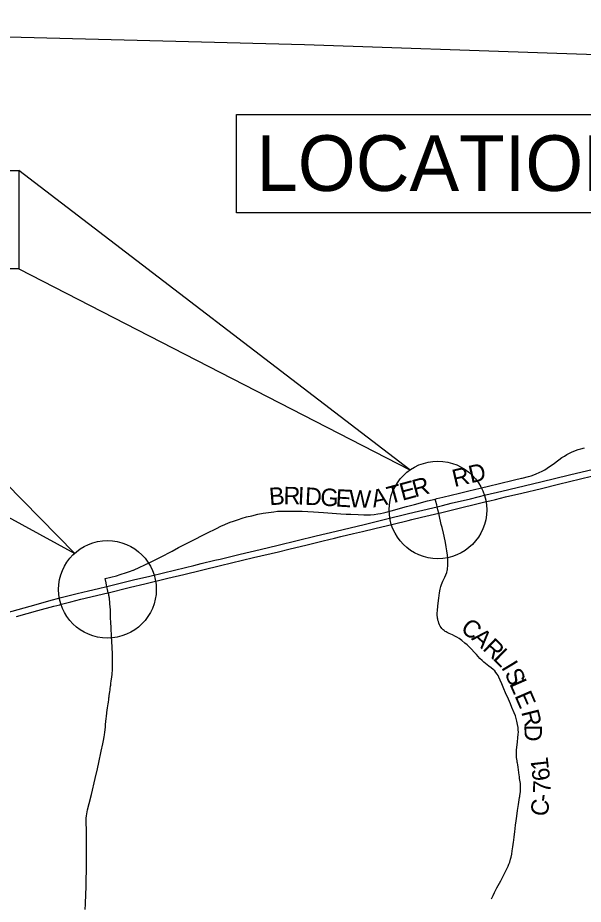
# Model space of a CAD drawing. Extents: x -29.6 to 34, y 0 to 22.
# Drawn here: x -14.201 to -12.475, y 3.392 to 6.1 of the extents above; entities that cross this region are included whole.
import ezdxf

# ---------------------------------------------------------------- set-up
doc = ezdxf.new("R2010")
doc.units = 0
for name, color, linetype in [('BR_P_Gen_Text', 7, 'Continuous'), ('Default', 7, 'Continuous'), ('GM_X_County_Road', 7, 'Continuous'), ('GM_X_County_Road_Text', 7, 'Continuous'), ('GM_X_Interstate_Location', 7, 'Continuous'), ('GM_X_Interstate_Route', 7, 'Continuous'), ('GM_X_Township', 7, 'Continuous'), ('GM_X_US_Route', 7, 'Continuous')]:
    doc.layers.add(name, color=color, linetype=linetype)

msp = doc.modelspace()

# ---------------------------------------------------------------- linework, layer by layer
at = {"layer": 'BR_P_Gen_Text'}
for points in [[(-13.5333, 5.8042), (-12.1246, 5.8042), (-12.1246, 5.504), (-13.5333, 5.504)], [(-15.6064, 5.6331), (-14.1976, 5.6331), (-14.1976, 5.3329), (-15.6064, 5.3329)], [(-14.1976, 5.6331), (-14.1976, 5.3329), (-13.0043, 4.7188)], [(-14.6646, 5.1118), (-14.6646, 4.8115), (-14.027, 4.4641)]]:
    msp.add_lwpolyline(points, close=True, dxfattribs=at)
at = {"layer": 'Default'}
for centre in [(-12.9184, 4.5966), (-13.9274, 4.3541)]:
    msp.add_circle(centre, 0.149, dxfattribs=at)
at = {"layer": 'GM_X_County_Road'}
for points in [[(-12.6637, 4.6933), (-12.6607, 4.694), (-12.6421, 4.6986), (-12.6332, 4.7012), (-12.6255, 4.7039), (-12.6185, 4.7066), (-12.6089, 4.7108), (-12.6, 4.715), (-12.5924, 4.7192), (-12.585, 4.7237), (-12.5773, 4.7289), (-12.5665, 4.7368), (-12.5488, 4.7501), (-12.5398, 4.7566), (-12.5324, 4.7613), (-12.5243, 4.766), (-12.517, 4.7698), (-12.5101, 4.7729), (-12.4982, 4.7779), (-12.49, 4.781), (-12.4817, 4.7837), (-12.471, 4.7865)], [(-12.9269, 4.6299), (-12.9217, 4.6312), (-12.9036, 4.6356), (-12.8775, 4.6419), (-12.852, 4.648), (-12.8243, 4.6546), (-12.7898, 4.663), (-12.7603, 4.6699), (-12.7349, 4.6763), (-12.6845, 4.6884), (-12.6637, 4.6933)], [(-13.5495, 4.5601), (-13.5451, 4.5618), (-13.5274, 4.5679), (-13.5163, 4.5714), (-13.5028, 4.5751), (-13.487, 4.5791), (-13.4682, 4.5834), (-13.4516, 4.5868), (-13.4361, 4.5893), (-13.4199, 4.5913), (-13.4082, 4.5924), (-13.3995, 4.593), (-13.3867, 4.5934), (-13.3721, 4.5934), (-13.3552, 4.5932), (-13.333, 4.5924), (-13.2981, 4.5906), (-13.2679, 4.5887), (-13.2417, 4.5872), (-13.2144, 4.5852), (-13.1981, 4.5842), (-13.1842, 4.5837), (-13.1621, 4.5826), (-13.1446, 4.5819), (-13.1336, 4.5818), (-13.1238, 4.5822), (-13.1133, 4.5831), (-13.1018, 4.5845), (-13.0938, 4.5858), (-13.0842, 4.5878), (-13.0763, 4.5897), (-13.0611, 4.5938), (-13.014, 4.607), (-12.9899, 4.6137), (-12.9505, 4.624), (-12.9269, 4.6299)], [(-12.908, 4.5526), (-12.9148, 4.5814), (-12.9161, 4.5869), (-12.9184, 4.5966), (-12.9208, 4.6064), (-12.9222, 4.6119), (-12.9248, 4.622), (-12.9269, 4.6299)], [(-13.772, 4.4496), (-13.7655, 4.4529), (-13.7303, 4.4711), (-13.7101, 4.4815), (-13.6739, 4.5003), (-13.6236, 4.5261), (-13.5948, 4.5402), (-13.5817, 4.5466), (-13.5695, 4.5522), (-13.5576, 4.5571), (-13.5495, 4.5601)], [(-12.8895, 4.4142), (-12.8887, 4.4181), (-12.8879, 4.4257), (-12.8877, 4.4326), (-12.8878, 4.4396), (-12.8883, 4.4489), (-12.8892, 4.4582), (-12.8909, 4.4715), (-12.8928, 4.4836), (-12.8941, 4.4911), (-12.8963, 4.5019), (-12.9015, 4.5257), (-12.9056, 4.5426), (-12.908, 4.5526)], [(-13.8492, 4.4126), (-13.8477, 4.4132), (-13.8285, 4.4215), (-13.8153, 4.4277), (-13.7955, 4.4376), (-13.772, 4.4496)], [(-12.7553, 3.4088), (-12.7502, 3.4197), (-12.7459, 3.428), (-12.7382, 3.4429), (-12.7268, 3.4639), (-12.7214, 3.4742), (-12.7173, 3.4819), (-12.7151, 3.486), (-12.7088, 3.4985), (-12.7038, 3.509), (-12.7015, 3.5144), (-12.6991, 3.5209), (-12.6963, 3.5298), (-12.6946, 3.5366), (-12.6929, 3.5452), (-12.6912, 3.5561), (-12.6896, 3.5676), (-12.6876, 3.582), (-12.6869, 3.5883), (-12.6858, 3.5986), (-12.684, 3.614), (-12.6829, 3.6238), (-12.6816, 3.6341), (-12.6799, 3.6468), (-12.6778, 3.6618), (-12.6755, 3.6786), (-12.6726, 3.6976), (-12.6693, 3.7183), (-12.6686, 3.7215), (-12.6682, 3.7243), (-12.6665, 3.7356), (-12.6661, 3.7407), (-12.666, 3.7548), (-12.6662, 3.7586), (-12.6664, 3.7609), (-12.6691, 3.7768), (-12.6697, 3.7815), (-12.6713, 3.7942), (-12.6725, 3.8036), (-12.6736, 3.8104), (-12.6748, 3.8191), (-12.6755, 3.8231), (-12.6758, 3.8242), (-12.676, 3.8253), (-12.6769, 3.8304), (-12.6781, 3.8409), (-12.6787, 3.849), (-12.6788, 3.856), (-12.6786, 3.8629), (-12.6777, 3.8722), (-12.6768, 3.8791), (-12.6755, 3.8884), (-12.674, 3.9005), (-12.6731, 3.9115), (-12.6728, 3.9185), (-12.6731, 3.9255), (-12.6738, 3.9325), (-12.6753, 3.9417), (-12.6773, 3.9514), (-12.6794, 3.9598), (-12.6818, 3.9676), (-12.6851, 3.977), (-12.6923, 3.9937), (-12.6969, 4.0045), (-12.7031, 4.0189), (-12.712, 4.0384), (-12.7171, 4.0499), (-12.7237, 4.0656), (-12.7285, 4.0769), (-12.7325, 4.0859), (-12.7348, 4.0906), (-12.7378, 4.0956), (-12.7412, 4.1004), (-12.745, 4.1048), (-12.7496, 4.1093), (-12.7557, 4.1146), (-12.7626, 4.1193), (-12.7733, 4.1272), (-12.7784, 4.1318), (-12.7837, 4.1365), (-12.7905, 4.1432), (-12.8007, 4.1547), (-12.8078, 4.1628), (-12.8155, 4.1713), (-12.8225, 4.1786), (-12.8287, 4.1842), (-12.8363, 4.1902), (-12.8456, 4.1976), (-12.8539, 4.2041), (-12.8604, 4.2081), (-12.8665, 4.2114), (-12.8737, 4.2151), (-12.8837, 4.2196), (-12.89, 4.2226), (-12.8931, 4.2242), (-12.896, 4.2259), (-12.8975, 4.2268), (-12.8993, 4.2282), (-12.902, 4.2304), (-12.9037, 4.232), (-12.9061, 4.2345), (-12.9086, 4.2377), (-12.9112, 4.2416), (-12.9137, 4.2462), (-12.9155, 4.2505), (-12.917, 4.2555), (-12.9182, 4.26), (-12.919, 4.2635), (-12.9195, 4.2657), (-12.92, 4.2686), (-12.9204, 4.2756), (-12.9204, 4.2826), (-12.92, 4.2889), (-12.9184, 4.304), (-12.9154, 4.3271), (-12.9132, 4.3433), (-12.9113, 4.3548), (-12.9095, 4.3627), (-12.9077, 4.3689), (-12.9058, 4.3738), (-12.9034, 4.3791), (-12.8971, 4.3915), (-12.894, 4.3985), (-12.8916, 4.4056), (-12.8901, 4.4113), (-12.8895, 4.4142)], [(-13.9347, 4.3868), (-13.9175, 4.3912), (-13.9, 4.3956), (-13.8883, 4.3991), (-13.8689, 4.4052), (-13.8601, 4.4083), (-13.8492, 4.4126)], [(-13.9206, 4.3181), (-13.9208, 4.3203), (-13.9212, 4.3225), (-13.9216, 4.327), (-13.9221, 4.3298), (-13.9226, 4.3332), (-13.923, 4.3348), (-13.9236, 4.3382), (-13.9248, 4.3438), (-13.9258, 4.3483), (-13.9292, 4.3631), (-13.9302, 4.3672), (-13.9318, 4.3739), (-13.9347, 4.3868)], [(-13.9953, 3.376), (-13.9945, 3.3926), (-13.9942, 3.4037), (-13.9938, 3.413), (-13.9934, 3.4212), (-13.993, 3.4316), (-13.9929, 3.4368), (-13.9928, 3.4444), (-13.9922, 3.4746), (-13.9918, 3.4891), (-13.9917, 3.5136), (-13.9917, 3.5346), (-13.9918, 3.5497), (-13.9916, 3.5713), (-13.9912, 3.5911), (-13.9913, 3.6033), (-13.9918, 3.6213), (-13.9926, 3.6394), (-13.9927, 3.6499), (-13.9925, 3.6552), (-13.9917, 3.6622), (-13.9906, 3.6685), (-13.9879, 3.6805), (-13.983, 3.7003), (-13.9765, 3.7281), (-13.9653, 3.7763), (-13.9582, 3.8058), (-13.9537, 3.8257), (-13.9464, 3.8604), (-13.942, 3.8821), (-13.9398, 3.8929), (-13.9378, 3.9038), (-13.9369, 3.9095), (-13.9358, 3.9182), (-13.9349, 3.9251), (-13.9338, 3.9343), (-13.9332, 3.94), (-13.932, 3.9515), (-13.9311, 3.959), (-13.9302, 3.9671), (-13.9279, 3.9862), (-13.9273, 3.9908), (-13.9262, 3.9994), (-13.9255, 4.004), (-13.9247, 4.0103), (-13.9237, 4.0166), (-13.9228, 4.0229), (-13.9224, 4.0257), (-13.9217, 4.0303), (-13.9203, 4.0407), (-13.9194, 4.047), (-13.9189, 4.0504), (-13.9177, 4.0585), (-13.9173, 4.0614), (-13.9166, 4.0677), (-13.9156, 4.0734), (-13.9148, 4.0804), (-13.9141, 4.0855), (-13.9139, 4.0867), (-13.9134, 4.0936), (-13.9128, 4.0994), (-13.9124, 4.1057), (-13.9119, 4.1162), (-13.9119, 4.1254), (-13.9122, 4.1406), (-13.9125, 4.1556), (-13.9134, 4.1781), (-13.9151, 4.2103), (-13.9164, 4.2362), (-13.9171, 4.2535), (-13.9177, 4.2663), (-13.9179, 4.275), (-13.918, 4.2849), (-13.9184, 4.2901), (-13.9192, 4.3022), (-13.9197, 4.3085), (-13.9199, 4.3111), (-13.9201, 4.3127), (-13.9202, 4.3148), (-13.9205, 4.317), (-13.9206, 4.3181)]]:
    msp.add_lwpolyline(points, dxfattribs=at)
at = {"layer": 'GM_X_Interstate_Route'}
for points in [[(-14.2365, 4.2822), (-14.1452, 4.3082), (-14.1065, 4.3189), (-14.0688, 4.3288), (-14.0203, 4.3412), (-13.9857, 4.3494), (-13.9551, 4.3568), (-13.9292, 4.3631), (-13.8969, 4.371), (-13.8482, 4.3828), (-13.7977, 4.3948), (-13.7558, 4.4049), (-13.6896, 4.421), (-13.6636, 4.4273), (-13.6415, 4.4326), (-13.5996, 4.4428), (-13.5832, 4.4468), (-13.5225, 4.4612), (-13.4614, 4.476), (-13.4059, 4.4892), (-13.2898, 4.5173), (-13.2286, 4.5321), (-13.1437, 4.5525), (-13.0786, 4.5682), (-13.0084, 4.5853), (-12.9342, 4.603), (-12.9212, 4.6063), (-12.9042, 4.6105), (-12.8776, 4.6169), (-12.8193, 4.6308), (-12.7717, 4.6425), (-12.723, 4.6542), (-12.6296, 4.6766), (-12.5667, 4.6918), (-12.5124, 4.705), (-12.4478, 4.7204)], [(-14.2047, 4.271), (-14.1402, 4.2893), (-14.0907, 4.3027), (-14.0733, 4.3073), (-14.0722, 4.3076), (-14.0395, 4.3161), (-14.009, 4.3238), (-13.9263, 4.3437), (-13.9248, 4.344), (-13.9248, 4.344), (-13.9093, 4.3477), (-13.877, 4.3555), (-13.8566, 4.3604), (-13.813, 4.3708), (-13.7428, 4.3878), (-13.6941, 4.3995), (-13.582, 4.4267), (-13.4818, 4.4509), (-13.4047, 4.4692), (-13.3736, 4.4768), (-13.3175, 4.4904), (-13.2688, 4.5021), (-13.2343, 4.5105), (-13.215, 4.5151), (-13.1765, 4.5244), (-13.1482, 4.5311), (-13.1108, 4.5401), (-13.0553, 4.5534), (-13.0088, 4.5646), (-12.9981, 4.5672), (-12.9681, 4.5745), (-12.9161, 4.5869), (-12.9103, 4.5883), (-12.8944, 4.5921), (-12.8537, 4.6019), (-12.7993, 4.615), (-12.7749, 4.6209), (-12.7597, 4.6246), (-12.7421, 4.6288), (-12.7116, 4.6363), (-12.6623, 4.6481), (-12.6022, 4.6625), (-12.5507, 4.6751), (-12.4828, 4.6916), (-12.416, 4.7078)]]:
    msp.add_lwpolyline(points, dxfattribs=at)
at = {"layer": 'GM_X_Township'}
msp.add_lwpolyline([(-16.907, 6.0998), (-16.7922, 6.098), (-15.3983, 6.0749), (-14.5953, 6.0489), (-14.3095, 6.0432), (-13.3257, 6.0175), (-12.5552, 5.9919), (-12.2845, 5.982)], dxfattribs=at)
at = {"layer": 'GM_X_US_Route'}
msp.add_lwpolyline([(-14.2047, 4.271), (-14.1402, 4.2893), (-14.0907, 4.3027), (-14.0733, 4.3073), (-14.0722, 4.3076), (-14.0395, 4.3161), (-14.009, 4.3238), (-13.9263, 4.3437), (-13.9248, 4.344), (-13.9248, 4.344), (-13.9093, 4.3477), (-13.877, 4.3555), (-13.8566, 4.3604), (-13.813, 4.3708), (-13.7428, 4.3878), (-13.6941, 4.3995), (-13.582, 4.4267), (-13.4818, 4.4509), (-13.4047, 4.4692), (-13.3736, 4.4768), (-13.3175, 4.4904), (-13.2688, 4.5021), (-13.2343, 4.5105), (-13.215, 4.5151), (-13.1765, 4.5244), (-13.1482, 4.5311), (-13.1108, 4.5401), (-13.0553, 4.5534), (-13.0088, 4.5646), (-12.9981, 4.5672), (-12.9681, 4.5745), (-12.9161, 4.5869), (-12.9103, 4.5883), (-12.8944, 4.5921), (-12.8537, 4.6019), (-12.7993, 4.615), (-12.7749, 4.6209), (-12.7597, 4.6246), (-12.7421, 4.6288), (-12.7116, 4.6363), (-12.6623, 4.6481), (-12.6022, 4.6625), (-12.5507, 4.6751), (-12.4828, 4.6916), (-12.416, 4.7078)], dxfattribs=at)

# ---------------------------------------------------------------- texts
at = {"layer": 'BR_P_Gen_Text'}
msp.add_text('LOCATION 1', height=0.17, dxfattribs=at).set_placement((-13.4726, 5.5708))
at = {"layer": 'GM_X_County_Road_Text'}
for s, height, rotation, p in [('RD', 0.05327, 13.2138, (-12.8679, 4.6661)), ('E', 0.0533, 15.0376, (-13.0273, 4.6244)), ('R', 0.0533, 14.989, (-12.9889, 4.6347)), ('B', 0.0533, 4.3959, (-13.432, 4.6107)), ('R', 0.0533, 359.5212, (-13.3899, 4.614)), ('I', 0.0533, 357.5435, (-13.347, 4.6136)), ('D', 0.0533, 356.9161, (-13.3254, 4.6127)), ('G', 0.0533, 356.5408, (-13.2786, 4.6102)), ('E', 0.0533, 356.5849, (-13.2316, 4.6073)), ('W', 0.0533, 358.0596, (-13.1904, 4.6049)), ('A', 0.0533, 11.2129, (-13.1157, 4.6039)), ('T', 0.0533, 15.223, (-13.0656, 4.614)), ('C', 0.0533, 322.4673, (-12.8523, 4.2285)), ('A', 0.0533, 317.3318, (-12.8186, 4.2027)), ('R', 0.0533, 316.4822, (-12.7842, 4.171)), ('L', 0.0533, 315.1121, (-12.7528, 4.1412)), ('I', 0.0533, 301.1432, (-12.7266, 4.1157)), ('S', 0.0533, 294.731, (-12.7161, 4.0984)), ('L', 0.0533, 293.6544, (-12.7011, 4.066)), ('E', 0.0533, 293.2937, (-12.6852, 4.0296)), ('R', 0.0533, 283.9501, (-12.6642, 3.9799)), ('D', 0.0533, 270.2368, (-12.6541, 3.9408)), ('1', 0.0533, 96.3356, (-12.5792, 3.805)), ('6', 0.0533, 97.968, (-12.5747, 3.7729)), ('7', 0.0533, 89.3746, (-12.5745, 3.7314)), ('C', 0.0533, 81.7203, (-12.5841, 3.6586)), ('-', 0.0533, 82.9001, (-12.5776, 3.7031))]:
    msp.add_text(s, height=height, rotation=rotation, dxfattribs=at).set_placement(p)
at = {"layer": 'GM_X_Interstate_Location'}
for s in ['.', '-', ',']:
    msp.add_text(s, height=0.000178, dxfattribs=at).set_placement((-12.6487, 4.6522))

doc.saveas('drawing.dxf')
